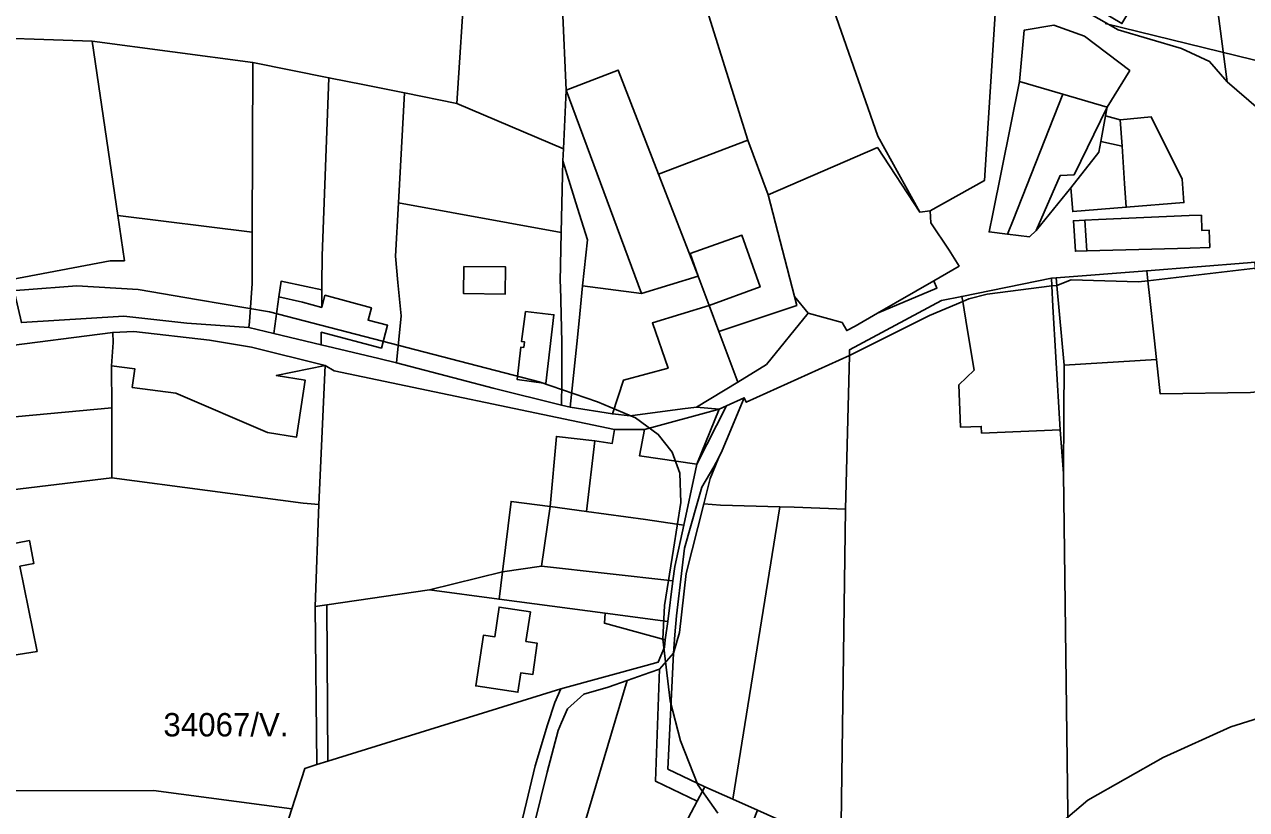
# Model space of a CAD drawing. Extents: x -535894 to -532834, y -1165802 to -1163645.
# Drawn here: x -534748.9 to -534487.4, y -1165239.2 to -1165071.2 of the extents above; entities that cross this region are included whole.
import ezdxf

# ---------------------------------------------------------------- set-up
doc = ezdxf.new("R2010")
doc.units = 0
for name, color, linetype in [('95560013', 7, 'Continuous'), ('95590013', 7, 'Continuous'), ('95600013', 7, 'Continuous'), ('95610013', 7, 'Continuous'), ('95640013', 7, 'Continuous'), ('95660013', 7, 'Continuous')]:
    doc.layers.add(name, color=color, linetype=linetype)

msp = doc.modelspace()

# ---------------------------------------------------------------- linework, layer by layer
at = {"layer": '95560013'}
for points in [[(-534659.81, -1164981.95), (-534642.59, -1164987.17), (-534638.87, -1165010.05), (-534634.53, -1165050.1), (-534632.91, -1165085.29), (-534633.52, -1165097.84), (-534656.31, -1165088.09), (-534654.53, -1165060.65), (-534655.57, -1165032.56)], [(-534583.6, -1165131.32), (-534584.1, -1165129.38), (-534581.2, -1165132.99), (-534590.09, -1165143.97), (-534596.23, -1165147.7), (-534600.27, -1165136.91)], [(-534555.22, -1165133.48), (-534548.1, -1165130.49), (-534547.14, -1165136.27), (-534545.65, -1165145.14), (-534548.9, -1165148.28), (-534548.58, -1165157.34), (-534544.12, -1165157.18), (-534544.07, -1165158.63), (-534527.28, -1165157.93), (-534526.56, -1165167.24), (-534525.52, -1165245.33), (-534574.14, -1165247.28), (-534573.16, -1165174.91), (-534572.34, -1165142)], [(-534552.61, -1165130.25), (-534548.29, -1165129.37), (-534548.1, -1165130.49), (-534555.22, -1165133.48), (-534572.34, -1165142), (-534572.31, -1165140.81)], [(-534638.24, -1165187.11), (-534610.1, -1165190.23), (-534611.2, -1165198.9), (-534624.61, -1165197.13), (-534647.31, -1165194.16), (-534646.59, -1165188.32)], [(-534609.98, -1165205.7), (-534611.16, -1165230.48), (-534603.26, -1165234.27), (-534604.9, -1165237.35), (-534613.84, -1165233.07), (-534612.98, -1165209.1)], [(-534612.98, -1165209.1), (-534613.84, -1165233.07), (-534604.9, -1165237.35), (-534613.26, -1165253.08), (-534625.77, -1165251.25), (-534631.5, -1165250.59), (-534619.86, -1165211.52), (-534615.03, -1165209.82)], [(-534619.86, -1165211.52), (-534631.5, -1165250.59), (-534635.8, -1165250.1), (-534641.82, -1165249.4), (-534639.72, -1165242.1), (-534636.98, -1165231.14), (-534634.63, -1165222.23), (-534633.92, -1165220.53), (-534632.69, -1165217.6), (-534629.15, -1165214.48), (-534623.99, -1165212.98)]]:
    msp.add_lwpolyline(points, close=True, dxfattribs=at)
msp.add_lwpolyline([(-534654.53, -1165060.65), (-534656.31, -1165088.09), (-534667.56, -1165085.84), (-534676.08, -1165084.13), (-534683.71, -1165082.61), (-534700.02, -1165079.35), (-534734.34, -1165074.8), (-534763.47, -1165073.76)], dxfattribs=at)
at = {"layer": '95590013'}
for points in [[(-534488.01, -1165020.91), (-534466.76, -1165022.45), (-534465.11, -1165045.38), (-534462.24, -1165085.02), (-534461.79, -1165091.28), (-534468.89, -1165092.92), (-534478.11, -1165095.05), (-534491.48, -1165083.48), (-534497.01, -1165041.71), (-534499.24, -1165024.85), (-534500.56, -1165014.81)], [(-534497.01, -1165041.71), (-534491.48, -1165083.48), (-534495.29, -1165079.16), (-534501.27, -1165076.38), (-534514.83, -1165072.36), (-534523.11, -1165067.68), (-534522.46, -1165066.03), (-534514.04, -1165071.03), (-534509.86, -1165063.98), (-534516.16, -1165060.24), (-534511.47, -1165040.97), (-534503.31, -1165041.78), (-534498.13, -1165041.73)], [(-534540.87, -1165064.35), (-534543.46, -1165104.62), (-534555.08, -1165111.1), (-534557.29, -1165111.36), (-534566.26, -1165095.11), (-534578.22, -1165060.77)], [(-534763.47, -1165073.76), (-534734.34, -1165074.8), (-534728.88, -1165112.1), (-534727.46, -1165121.76), (-534730.52, -1165121.79), (-534751.61, -1165125.75)], [(-534734.34, -1165074.8), (-534700.02, -1165079.35), (-534700.11, -1165115.65), (-534728.88, -1165112.1)], [(-534700.02, -1165079.35), (-534683.71, -1165082.61), (-534685.15, -1165120.7), (-534685.21, -1165126.74), (-534685.22, -1165127.97), (-534688.56, -1165127.27), (-534693.94, -1165126.15), (-534694.4, -1165129.48), (-534695.46, -1165137.34), (-534700.81, -1165136.05), (-534700.73, -1165134.84), (-534700.15, -1165126.59), (-534700.12, -1165119.16), (-534700.11, -1165115.65)], [(-534632.91, -1165085.29), (-534621.81, -1165080.98), (-534613.17, -1165103.24), (-534604.71, -1165125.03), (-534616.82, -1165128.79)], [(-534683.71, -1165082.61), (-534676.08, -1165084.13), (-534667.56, -1165085.84), (-534668.84, -1165109.34), (-534669.47, -1165120.79), (-534668.93, -1165126.38), (-534668.22, -1165133.57), (-534669.22, -1165143.61), (-534673.06, -1165142.69), (-534685.39, -1165139.75), (-534685.34, -1165137.05), (-534672.46, -1165140.44), (-534671.16, -1165135.57), (-534675.31, -1165134.45), (-534674.61, -1165131.83), (-534684.55, -1165129.15), (-534685.25, -1165131.75), (-534685.22, -1165127.97), (-534685.21, -1165126.74), (-534685.15, -1165120.7)], [(-534526.65, -1165086.13), (-534537.31, -1165113.11), (-534538.48, -1165116.07), (-534542.44, -1165115.58), (-534541.67, -1165111.7), (-534535.98, -1165083.39)], [(-534667.56, -1165085.84), (-534656.31, -1165088.09), (-534633.52, -1165097.84), (-534633.69, -1165100.36), (-534634.01, -1165115.7), (-534668.84, -1165109.34)], [(-534633.52, -1165097.84), (-534632.91, -1165085.29), (-534616.82, -1165128.79), (-534629.43, -1165127.15), (-534628.41, -1165117.31), (-534630.5, -1165110.5), (-534633.69, -1165100.36)], [(-534517.17, -1165088.92), (-534524.28, -1165103.39), (-534527.23, -1165103.5), (-534532.37, -1165115.29), (-534533.82, -1165116.64), (-534538.48, -1165116.07), (-534537.31, -1165113.11), (-534526.65, -1165086.13)], [(-534517.52, -1165090.78), (-534518.52, -1165096.23), (-534518.94, -1165098.54), (-534524.95, -1165106.16), (-534532.37, -1165115.29), (-534527.23, -1165103.5), (-534524.28, -1165103.39), (-534517.17, -1165088.92)], [(-534613.17, -1165103.24), (-534594.05, -1165095.99), (-534589.74, -1165107.68), (-534584.1, -1165129.38), (-534583.6, -1165131.32), (-534600.27, -1165136.91), (-534602.37, -1165131.3), (-534591.44, -1165127.34), (-534595.34, -1165116.29), (-534606.42, -1165120.2), (-534604.71, -1165125.03)], [(-534528.11, -1165125.42), (-534508.71, -1165123.9), (-534508.47, -1165126.04), (-534510.46, -1165126.27), (-534524.87, -1165125.86), (-534527.96, -1165127.06)], [(-534529.13, -1165125.5), (-534528.11, -1165125.42), (-534527.96, -1165127.06), (-534529.03, -1165127.13)], [(-534510.46, -1165126.27), (-534508.47, -1165126.04), (-534508.07, -1165129.82), (-534507.16, -1165138.28), (-534506.66, -1165142.89), (-534526.42, -1165144.06), (-534527.96, -1165127.06), (-534524.87, -1165125.86)], [(-534529.03, -1165127.13), (-534527.96, -1165127.06), (-534526.42, -1165144.06), (-534526.49, -1165154.6), (-534526.56, -1165167.24), (-534527.28, -1165157.93), (-534528.17, -1165142.37), (-534528.78, -1165131.54)], [(-534602.37, -1165131.3), (-534600.27, -1165136.91), (-534596.23, -1165147.7), (-534605.04, -1165153.06), (-534608.06, -1165153.45), (-534619.23, -1165154.9), (-534623.03, -1165154.53), (-534620.7, -1165147.3), (-534611.13, -1165144.71), (-534614.5, -1165135.07)], [(-534730.19, -1165144.21), (-534725.23, -1165144.88), (-534725.77, -1165148.84), (-534716.45, -1165150.08), (-534696.83, -1165158.5), (-534690.66, -1165159.52), (-534688.78, -1165147.31), (-534694.96, -1165146.32), (-534684.51, -1165144.15), (-534685.89, -1165173.92), (-534688.37, -1165173.69), (-534689.23, -1165173.62), (-534730.12, -1165168.22), (-534730.17, -1165153.22)], [(-534684.51, -1165144.15), (-534682.61, -1165145.33), (-534622.58, -1165157.86), (-534623.09, -1165160.82), (-534626.83, -1165160.29), (-534635.03, -1165159.35), (-534636.37, -1165174.35), (-534644.72, -1165173.23), (-534646.59, -1165188.32), (-534662.22, -1165192.14), (-534684.12, -1165195.33), (-534686.67, -1165195.7), (-534685.89, -1165173.92)], [(-534730.17, -1165153.22), (-534730.12, -1165168.22), (-534773.45, -1165173.38), (-534774.56, -1165157.32), (-534764.6, -1165156.39), (-534764.14, -1165161.37), (-534756.67, -1165160.69), (-534757.12, -1165155.71)], [(-534635.03, -1165159.35), (-534626.83, -1165160.29), (-534628.59, -1165175.38), (-534636.37, -1165174.35)], [(-534644.72, -1165173.23), (-534636.37, -1165174.35), (-534638.24, -1165187.11), (-534646.59, -1165188.32)], [(-534599.92, -1165174.06), (-534587.22, -1165174.4), (-534597.25, -1165236.95), (-534603.26, -1165234.27), (-534611.16, -1165230.48), (-534609.98, -1165205.7), (-534608.72, -1165201.29), (-534607.25, -1165188.65), (-534603.51, -1165173.76)], [(-534587.22, -1165174.4), (-534584.13, -1165174.48), (-534573.16, -1165174.91), (-534574.14, -1165247.28), (-534591.99, -1165239.3), (-534597.25, -1165236.95)], [(-534662.22, -1165192.14), (-534646.59, -1165188.32), (-534647.31, -1165194.16)], [(-534611.2, -1165198.9), (-534611.73, -1165202.83), (-534624.76, -1165199.3), (-534624.61, -1165197.13)], [(-534761.05, -1165235.16), (-534721.27, -1165235.1), (-534691.61, -1165239), (-534700.96, -1165268.14), (-534719.29, -1165264.53), (-534730.57, -1165265.33), (-534763.18, -1165261.89)], [(-534603.26, -1165234.27), (-534597.25, -1165236.95), (-534591.99, -1165239.3), (-534623.17, -1165318.51), (-534633.83, -1165316.18), (-534637.1, -1165315.06), (-534627.97, -1165285.63), (-534627.83, -1165285.22), (-534624.62, -1165276.23), (-534613.26, -1165253.08), (-534604.9, -1165237.35)]]:
    msp.add_lwpolyline(points, close=True, dxfattribs=at)
at = {"layer": '95600013'}
for points in [[(-534526.42, -1165144.06), (-534506.66, -1165142.89), (-534505.88, -1165150.21), (-534486.55, -1165149.95), (-534482.37, -1165149.5), (-534479.49, -1165178.1), (-534474.69, -1165217.27), (-534470.72, -1165237.94), (-534490.64, -1165243.85), (-534498.4, -1165244.45), (-534504.24, -1165246.32), (-534515.07, -1165249.99), (-534525.69, -1165253.61), (-534525.52, -1165245.33), (-534526.56, -1165167.24), (-534526.49, -1165154.6)], [(-534773.45, -1165173.38), (-534730.12, -1165168.22), (-534689.23, -1165173.62), (-534688.37, -1165173.69), (-534685.89, -1165173.92), (-534686.67, -1165195.7), (-534686.31, -1165229.5), (-534688.84, -1165230.36), (-534691.61, -1165239), (-534721.27, -1165235.1), (-534761.05, -1165235.16), (-534760.2, -1165224.39), (-534765.68, -1165208.38), (-534746.16, -1165205.31), (-534749.82, -1165187.09), (-534746.85, -1165186.52), (-534747.79, -1165181.61), (-534772.09, -1165186.32)]]:
    msp.add_lwpolyline(points, close=True, dxfattribs=at)
at = {"layer": '95610013'}
for points in [[(-534584.13, -1165044.84), (-534579.64, -1165056.67), (-534578.22, -1165060.77), (-534566.26, -1165095.11), (-534557.29, -1165111.36), (-534566.34, -1165097.55), (-534589.74, -1165107.68), (-534594.05, -1165095.99), (-534609.24, -1165047.46)], [(-534609.24, -1165047.46), (-534594.05, -1165095.99), (-534613.17, -1165103.24), (-534621.81, -1165080.98), (-534632.91, -1165085.29), (-534634.53, -1165050.1)], [(-534647.31, -1165194.16), (-534624.61, -1165197.13), (-534624.76, -1165199.3), (-534611.73, -1165202.83), (-534611.88, -1165204.39), (-534613.23, -1165207.6), (-534615.85, -1165208.32), (-534634.06, -1165213.3), (-534683.94, -1165228.77), (-534684.12, -1165195.33), (-534662.22, -1165192.14)], [(-534640.55, -1165196.85), (-534647.3, -1165195.84), (-534648.22, -1165202.21), (-534650.63, -1165201.84), (-534652.28, -1165212.72), (-534643.25, -1165214.06), (-534642.63, -1165209.88), (-534640.07, -1165210.25), (-534639.12, -1165203.57), (-534641.54, -1165203.19)], [(-534635.35, -1165216.23), (-534636.93, -1165221.04), (-534639.56, -1165229.81), (-534642.21, -1165240.82), (-534647.4, -1165260.65), (-534648.68, -1165264.17), (-534671.96, -1165259.81), (-534672.89, -1165264.71), (-534673.41, -1165267.52), (-534674.85, -1165275.19), (-534675.39, -1165278.09), (-534700.96, -1165268.14), (-534691.61, -1165239), (-534688.84, -1165230.36), (-534686.31, -1165229.5), (-534683.94, -1165228.77), (-534634.06, -1165213.3)]]:
    msp.add_lwpolyline(points, close=True, dxfattribs=at)
at = {"layer": '95640013'}
for points in [[(-534466.76, -1165022.45), (-534488.01, -1165020.91), (-534500.56, -1165014.81), (-534508.03, -1165014.6), (-534515.85, -1165014.39), (-534517.16, -1165014.36), (-534529.63, -1165017.43), (-534533.96, -1165023.42), (-534534.04, -1165025.41), (-534537.78, -1165033.97), (-534538.58, -1165038), (-534540.03, -1165045.35), (-534538.55, -1165053.24), (-534536.12, -1165058.39), (-534533.08, -1165062.06), (-534523.11, -1165067.68), (-534514.83, -1165072.36), (-534501.27, -1165076.38), (-534495.29, -1165079.16), (-534491.48, -1165083.48), (-534478.11, -1165095.05)], [(-534487.16, -1165122.22), (-534508.71, -1165123.9), (-534528.11, -1165125.42), (-534529.13, -1165125.5), (-534548.29, -1165129.37), (-534552.61, -1165130.25), (-534572.31, -1165140.81), (-534572.34, -1165142), (-534594.43, -1165152.01), (-534594.86, -1165151.07), (-534598.63, -1165152.79), (-534600.19, -1165153.5), (-534605.04, -1165153.06), (-534596.23, -1165147.7), (-534590.09, -1165143.97), (-534581.2, -1165132.99), (-534573.9, -1165134.95), (-534572.91, -1165136.68), (-534571.13, -1165135.75), (-534566.36, -1165133), (-534553.63, -1165127.61), (-534554.3, -1165126.03), (-534548.88, -1165122.89), (-534551, -1165119.46), (-534554.9, -1165113.66), (-534555.08, -1165111.1), (-534543.46, -1165104.62), (-534540.87, -1165064.35)], [(-534749.51, -1165134.97), (-534727.56, -1165133.63), (-534714.12, -1165135.13), (-534700.81, -1165136.05), (-534695.46, -1165137.34), (-534685.39, -1165139.75), (-534673.06, -1165142.69), (-534669.22, -1165143.61), (-534655.64, -1165147.16), (-534648.54, -1165149.03), (-534633.92, -1165152.65), (-534632.07, -1165153.06), (-534623.03, -1165154.53), (-534619.23, -1165154.9), (-534608.06, -1165153.45), (-534605.04, -1165153.06), (-534600.19, -1165153.5), (-534616.15, -1165157.87), (-534622.58, -1165157.86), (-534682.61, -1165145.33), (-534684.51, -1165144.15), (-534700.3, -1165140.27), (-534709.27, -1165138.78), (-534725.42, -1165136.87), (-534729.95, -1165137.1), (-534754.46, -1165140.25)], [(-534642.21, -1165240.82), (-534639.56, -1165229.81), (-534636.93, -1165221.04), (-534635.35, -1165216.23), (-534634.06, -1165213.3), (-534615.85, -1165208.32), (-534613.23, -1165207.6), (-534611.88, -1165204.39), (-534611.73, -1165202.83), (-534611.2, -1165198.9), (-534610.1, -1165190.23), (-534609.72, -1165187.18), (-534607.79, -1165178.29), (-534605.25, -1165166.64), (-534604.96, -1165165.29), (-534598.63, -1165152.79), (-534594.86, -1165151.07), (-534598.66, -1165160.11), (-534599.6, -1165162.33), (-534600.32, -1165164.01), (-534601.37, -1165165.82), (-534603.9, -1165170.17), (-534604.88, -1165173.65), (-534607.6, -1165183.25), (-534608.15, -1165187.48), (-534609.36, -1165197.7), (-534609.68, -1165201.8), (-534609.98, -1165205.7), (-534612.98, -1165209.1), (-534615.03, -1165209.82), (-534619.86, -1165211.52), (-534623.99, -1165212.98), (-534629.15, -1165214.48), (-534632.69, -1165217.6), (-534633.92, -1165220.53), (-534634.63, -1165222.23), (-534636.98, -1165231.14), (-534639.72, -1165242.1)]]:
    msp.add_lwpolyline(points, dxfattribs=at)
for points in [[(-534528.58, -1165071.39), (-534534.97, -1165072.45), (-534535.98, -1165083.39), (-534541.67, -1165111.7), (-534542.44, -1165115.58), (-534538.48, -1165116.07), (-534533.82, -1165116.64), (-534532.37, -1165115.29), (-534524.95, -1165106.16), (-534524.55, -1165111.25), (-534513.11, -1165110.32), (-534500.76, -1165109.3), (-534501.16, -1165104.28), (-534507.77, -1165091), (-534514.4, -1165091.6), (-534517.52, -1165090.78), (-534517.17, -1165088.92), (-534512.37, -1165081.09), (-534522.06, -1165073.71)], [(-534528.58, -1165071.39), (-534522.06, -1165073.71), (-534512.37, -1165081.09), (-534517.17, -1165088.92), (-534526.65, -1165086.13), (-534535.98, -1165083.39), (-534534.97, -1165072.45)], [(-534514.4, -1165091.6), (-534514.01, -1165097.25), (-534518.52, -1165096.23), (-534517.52, -1165090.78)], [(-534514.4, -1165091.6), (-534507.77, -1165091), (-534501.16, -1165104.28), (-534500.76, -1165109.3), (-534513.11, -1165110.32), (-534513.46, -1165105.26), (-534514.01, -1165097.25)], [(-534589.74, -1165107.68), (-534566.34, -1165097.55), (-534557.29, -1165111.36), (-534555.08, -1165111.1), (-534554.9, -1165113.66), (-534551, -1165119.46), (-534548.88, -1165122.89), (-534554.3, -1165126.03), (-534566.36, -1165133), (-534571.13, -1165135.75), (-534572.91, -1165136.68), (-534573.9, -1165134.95), (-534581.2, -1165132.99), (-534584.1, -1165129.38)], [(-534518.52, -1165096.23), (-534514.01, -1165097.25), (-534513.46, -1165105.26), (-534513.11, -1165110.32), (-534524.55, -1165111.25), (-534524.95, -1165106.16), (-534518.94, -1165098.54)], [(-534630.5, -1165110.5), (-534628.41, -1165117.31), (-534629.43, -1165127.15), (-534630.05, -1165133.13), (-534630.54, -1165138.14), (-534632.07, -1165153.06), (-534633.92, -1165152.65), (-534633.9, -1165147.68), (-534633.88, -1165139.16), (-534634.19, -1165127.24), (-534634.22, -1165126.18), (-534634.01, -1165115.7), (-534633.69, -1165100.36)], [(-534634.01, -1165115.7), (-534634.22, -1165126.18), (-534634.19, -1165127.24), (-534633.88, -1165139.16), (-534633.9, -1165147.68), (-534633.92, -1165152.65), (-534648.54, -1165149.03), (-534655.64, -1165147.16), (-534669.22, -1165143.61), (-534668.22, -1165133.57), (-534668.93, -1165126.38), (-534669.47, -1165120.79), (-534668.84, -1165109.34)], [(-534728.88, -1165112.1), (-534700.11, -1165115.65), (-534700.12, -1165119.16), (-534700.15, -1165126.59), (-534700.73, -1165134.84), (-534700.81, -1165136.05), (-534714.12, -1165135.13), (-534727.56, -1165133.63), (-534749.51, -1165134.97), (-534751.61, -1165125.75), (-534730.52, -1165121.79), (-534727.46, -1165121.76)], [(-534499.64, -1165112.1), (-534519.03, -1165112.95), (-534521.96, -1165113.08), (-534524.4, -1165113.2), (-534523.98, -1165119.71), (-534521.53, -1165119.64), (-534507.64, -1165119.26), (-534499.45, -1165119.04), (-534495.25, -1165118.92), (-534495.36, -1165115.23), (-534496.95, -1165115.27), (-534497.04, -1165112.02)], [(-534521.96, -1165113.08), (-534521.53, -1165119.64), (-534523.98, -1165119.71), (-534524.4, -1165113.2)], [(-534499.64, -1165112.1), (-534497.04, -1165112.02), (-534496.95, -1165115.27), (-534495.36, -1165115.23), (-534495.25, -1165118.92), (-534499.45, -1165119.04), (-534507.64, -1165119.26), (-534521.53, -1165119.64), (-534521.96, -1165113.08), (-534519.03, -1165112.95)], [(-534595.34, -1165116.29), (-534591.44, -1165127.34), (-534602.37, -1165131.3), (-534604.71, -1165125.03), (-534606.42, -1165120.2)], [(-534654.84, -1165122.97), (-534645.89, -1165123.06), (-534645.96, -1165128.89), (-534654.9, -1165128.79)], [(-534654.84, -1165122.97), (-534654.9, -1165128.79), (-534645.96, -1165128.89), (-534645.89, -1165123.06)], [(-534485.59, -1165122.03), (-534485.47, -1165123.31), (-534508.47, -1165126.04), (-534508.71, -1165123.9), (-534487.16, -1165122.22)], [(-534508.47, -1165126.04), (-534485.47, -1165123.31), (-534485.11, -1165127.29), (-534482.54, -1165147.81), (-534482.37, -1165149.5), (-534486.55, -1165149.95), (-534505.88, -1165150.21), (-534506.66, -1165142.89), (-534507.16, -1165138.28), (-534508.07, -1165129.82)], [(-534688.56, -1165127.27), (-534685.22, -1165127.97), (-534685.25, -1165131.75), (-534689.38, -1165130.63), (-534694.4, -1165129.48), (-534693.94, -1165126.15)], [(-534604.71, -1165125.03), (-534602.37, -1165131.3), (-534614.5, -1165135.07), (-534611.13, -1165144.71), (-534620.7, -1165147.3), (-534623.03, -1165154.53), (-534632.07, -1165153.06), (-534630.54, -1165138.14), (-534630.05, -1165133.13), (-534629.43, -1165127.15), (-534616.82, -1165128.79)], [(-534554.3, -1165126.03), (-534553.63, -1165127.61), (-534566.36, -1165133)], [(-534529.03, -1165127.13), (-534542.89, -1165128.92), (-534546.81, -1165129.93), (-534548.1, -1165130.49), (-534548.29, -1165129.37), (-534529.13, -1165125.5)], [(-534694.4, -1165129.48), (-534689.38, -1165130.63), (-534685.25, -1165131.75), (-534684.55, -1165129.15), (-534674.61, -1165131.83), (-534675.31, -1165134.45), (-534671.16, -1165135.57), (-534672.46, -1165140.44), (-534685.34, -1165137.05), (-534685.39, -1165139.75), (-534695.46, -1165137.34)], [(-534542.89, -1165128.92), (-534529.03, -1165127.13), (-534528.78, -1165131.54), (-534528.17, -1165142.37), (-534527.28, -1165157.93), (-534544.07, -1165158.63), (-534544.12, -1165157.18), (-534548.58, -1165157.34), (-534548.9, -1165148.28), (-534545.65, -1165145.14), (-534547.14, -1165136.27), (-534548.1, -1165130.49), (-534546.81, -1165129.93)], [(-534641.67, -1165132.6), (-534642.47, -1165139.03), (-534641.89, -1165139.1), (-534642.02, -1165140.28), (-534642.63, -1165140.21), (-534643.4, -1165147.16), (-534637.3, -1165147.98), (-534635.55, -1165133.32)], [(-534641.67, -1165132.6), (-534635.55, -1165133.32), (-534637.3, -1165147.98), (-534643.4, -1165147.16), (-534642.63, -1165140.21), (-534642.02, -1165140.28), (-534641.89, -1165139.1), (-534642.47, -1165139.03)], [(-534729.95, -1165137.1), (-534729.88, -1165139.24), (-534730.19, -1165144.21), (-534730.17, -1165153.22), (-534757.12, -1165155.71), (-534764.6, -1165156.39), (-534774.56, -1165157.32), (-534774.83, -1165153.47), (-534775.05, -1165150.33), (-534775.25, -1165147.5), (-534775.49, -1165144.03), (-534773.4, -1165143.64), (-534754.46, -1165140.25)], [(-534725.42, -1165136.87), (-534709.27, -1165138.78), (-534700.3, -1165140.27), (-534684.51, -1165144.15), (-534694.96, -1165146.32), (-534688.78, -1165147.31), (-534690.66, -1165159.52), (-534696.83, -1165158.5), (-534716.45, -1165150.08), (-534725.77, -1165148.84), (-534725.23, -1165144.88), (-534730.19, -1165144.21), (-534729.88, -1165139.24), (-534729.95, -1165137.1)], [(-534572.34, -1165142), (-534573.16, -1165174.91), (-534584.13, -1165174.48), (-534587.22, -1165174.4), (-534599.92, -1165174.06), (-534603.51, -1165173.76), (-534602.14, -1165168.33), (-534600.32, -1165164.01), (-534599.6, -1165162.33), (-534598.66, -1165160.11), (-534594.86, -1165151.07), (-534594.43, -1165152.01)], [(-534598.63, -1165152.79), (-534604.96, -1165165.29), (-534600.19, -1165153.5)], [(-534616.15, -1165157.87), (-534600.19, -1165153.5), (-534604.96, -1165165.29), (-534617.24, -1165163.5)], [(-534622.58, -1165157.86), (-534616.15, -1165157.87), (-534617.24, -1165163.5), (-534604.96, -1165165.29), (-534605.25, -1165166.64), (-534607.79, -1165178.29), (-534609.24, -1165178.08), (-534615.95, -1165177.07), (-534628.59, -1165175.38), (-534626.83, -1165160.29), (-534623.09, -1165160.82)], [(-534601.37, -1165165.82), (-534600.32, -1165164.01), (-534602.14, -1165168.33), (-534603.51, -1165173.76), (-534607.25, -1165188.65), (-534608.72, -1165201.29), (-534609.98, -1165205.7), (-534609.68, -1165201.8), (-534609.36, -1165197.7), (-534608.15, -1165187.48), (-534607.6, -1165183.25), (-534604.88, -1165173.65), (-534603.9, -1165170.17)], [(-534636.37, -1165174.35), (-534628.59, -1165175.38), (-534615.95, -1165177.07), (-534609.24, -1165178.08), (-534607.79, -1165178.29), (-534609.72, -1165187.18), (-534610.1, -1165190.23), (-534638.24, -1165187.11)], [(-534747.79, -1165181.61), (-534746.85, -1165186.52), (-534749.82, -1165187.09), (-534746.16, -1165205.31), (-534765.68, -1165208.38), (-534774.55, -1165209.78), (-534775.06, -1165207.15), (-534787.13, -1165209.49), (-534788.65, -1165201.64), (-534789.14, -1165199.14), (-534790.92, -1165189.96), (-534779.72, -1165187.79), (-534772.09, -1165186.32)], [(-534686.67, -1165195.7), (-534684.12, -1165195.33), (-534683.94, -1165228.77), (-534686.31, -1165229.5)], [(-534640.55, -1165196.85), (-534641.54, -1165203.19), (-534639.12, -1165203.57), (-534640.07, -1165210.25), (-534642.63, -1165209.88), (-534643.25, -1165214.06), (-534652.28, -1165212.72), (-534650.63, -1165201.84), (-534648.22, -1165202.21), (-534647.3, -1165195.84)]]:
    msp.add_lwpolyline(points, close=True, dxfattribs=at)
at = {"layer": '95660013'}
for points in [[(-534482.42, -1165079.6), (-534517.62, -1165071)], [(-534517.62, -1165071), (-534482.42, -1165079.6)], [(-534756.06, -1165128.5), (-534748.847, -1165127.956), (-534737.639, -1165127.111), (-534724.549, -1165127.901), (-534711.619, -1165130.09), (-534696.44, -1165132.66), (-534663.2, -1165141.32), (-534638.75, -1165147.69), (-534626.24, -1165151.91), (-534618.12, -1165155.34), (-534613.239, -1165158.905), (-534610.24, -1165162.67), (-534608.64, -1165167.21), (-534608.412, -1165173.45), (-534609.999, -1165183.45), (-534611.91, -1165195.48), (-534612.23, -1165202.72), (-534610.71, -1165215.87), (-534608.48, -1165224.47), (-534604.74, -1165233.86), (-534600.52, -1165239.92)], [(-534600.52, -1165239.92), (-534604.74, -1165233.86), (-534608.48, -1165224.47), (-534610.71, -1165215.87), (-534612.23, -1165202.72), (-534611.91, -1165195.48), (-534609.999, -1165183.45), (-534608.412, -1165173.45), (-534608.64, -1165167.21), (-534610.24, -1165162.67), (-534613.239, -1165158.905), (-534618.12, -1165155.34), (-534626.24, -1165151.91), (-534638.75, -1165147.69), (-534663.2, -1165141.32), (-534696.44, -1165132.66), (-534711.619, -1165130.09), (-534724.549, -1165127.901), (-534737.639, -1165127.111), (-534748.847, -1165127.956), (-534756.06, -1165128.5)], [(-534531.79, -1165246.05), (-534521.36, -1165237.13), (-534505.19, -1165228.05), (-534490.7, -1165221.44), (-534474.13, -1165216.26)], [(-534474.13, -1165216.26), (-534490.7, -1165221.44), (-534505.19, -1165228.05), (-534521.36, -1165237.13), (-534531.79, -1165246.05)]]:
    msp.add_lwpolyline(points, dxfattribs=at)

# ---------------------------------------------------------------- texts
msp.add_text('34067/V.', height=5, rotation=0, dxfattribs=at).set_placement((-534719.115, -1165223.504))

doc.saveas('drawing.dxf')
